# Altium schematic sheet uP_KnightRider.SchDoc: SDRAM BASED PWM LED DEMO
size A4; Engineer: SHOWELL; DocumentNumber: 1; Revision: 1.00; SheetNumber: 1; SheetTotal: 1
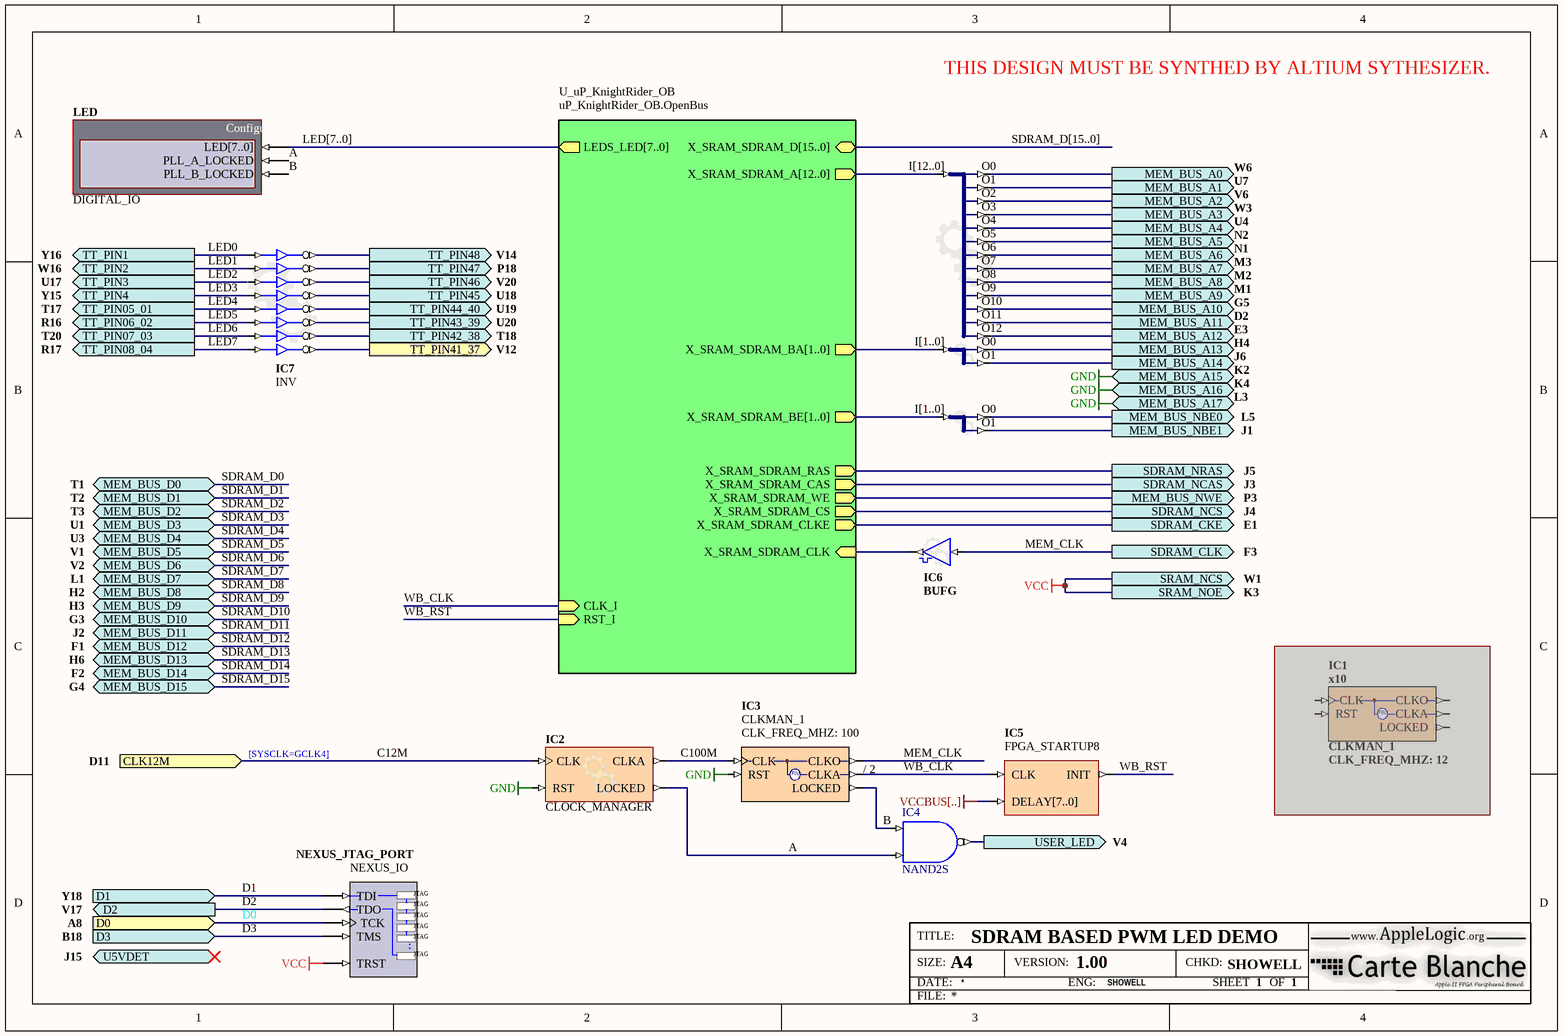
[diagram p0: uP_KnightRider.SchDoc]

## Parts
IC1  CLKMAN_1  CLK_FREQ_MHZ: 12  ClkA_Operation: x10  (masked out: inside a compile mask, not in the netlist)
IC2  CLOCK_MANAGER
IC3  CLKMAN_1  CLK_FREQ_MHZ: 100  ClkA_Operation: / 2
IC4  NAND2S
IC5  FPGA_STARTUP8
IC6  BUFG
IC7  INV
LED  DIGITAL_IO
NEXUS_JTAG_PORT  NEXUS_IO
U1011  BUS_JS  (value not drawn)
U1018  BUS_JS  (value not drawn)
U8011  BUS_JS  (value not drawn)

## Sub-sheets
U_uP_KnightRider_OB = uP_KnightRider_OB.OpenBus: LEDS_LED[7..0] (out), X_SRAM_SDRAM_D[15..0] (bidir), X_SRAM_SDRAM_A[12..0] (out), X_SRAM_SDRAM_BA[1..0] (out), X_SRAM_SDRAM_BE[1..0] (out), X_SRAM_SDRAM_RAS (out), X_SRAM_SDRAM_CAS (out), X_SRAM_SDRAM_WE (out), X_SRAM_SDRAM_CS (out), X_SRAM_SDRAM_CLKE (out), X_SRAM_SDRAM_CLK (in), RST_I (in), CLK_I (in)

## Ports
CLK12M (in, see D11), D0 (in, see A8), D1 (in, see Y18), D2 (out, see V17), D3 (in, see B18), MEM_BUS_A0 (out, see W6), MEM_BUS_A1 (out, see U7), MEM_BUS_A2 (out, see V6), MEM_BUS_A3 (out, see W3), MEM_BUS_A4 (out, see U4), MEM_BUS_A5 (out, see N2), MEM_BUS_A6 (out, see N1), MEM_BUS_A7 (out, see M3), MEM_BUS_A8 (out, see M2), MEM_BUS_A9 (out, see M1), MEM_BUS_A10 (out, see G5), MEM_BUS_A11 (out, see D2), MEM_BUS_A12 (out, see E3), MEM_BUS_A13 (out, see H4), MEM_BUS_A14 (out, see J6), MEM_BUS_A15 (out, see K2), MEM_BUS_A16 (out, see K4), MEM_BUS_A17 (out, see L3), MEM_BUS_D0 (bidir, see T1), MEM_BUS_D1 (bidir, see T2), MEM_BUS_D2 (bidir, see T3), MEM_BUS_D3 (bidir, see U1), MEM_BUS_D4 (bidir, see U3), MEM_BUS_D5 (bidir, see V1), MEM_BUS_D6 (bidir, see V2), MEM_BUS_D7 (bidir, see L1), MEM_BUS_D8 (bidir, see H2), MEM_BUS_D9 (bidir, see H3), MEM_BUS_D10 (bidir, see G3), MEM_BUS_D11 (bidir, see J2), MEM_BUS_D12 (bidir, see F1), MEM_BUS_D13 (bidir, see H6), MEM_BUS_D14 (bidir, see F2), MEM_BUS_D15 (bidir, see G4), MEM_BUS_NBE0 (out, see L5), MEM_BUS_NBE1 (out, see J1), MEM_BUS_NWE (out, see P3), SDRAM_CKE (out, see E1), SDRAM_CLK (out, see F3), SDRAM_NCAS (out, see J3), SDRAM_NCS (out, see J4), SDRAM_NRAS (out, see J5), SRAM_NCS (out, see W1), SRAM_NOE (out, see K3), TT_PIN1 (out, see Y16), TT_PIN2 (out, see W16), TT_PIN3 (out, see U17), TT_PIN4 (out, see Y15), TT_PIN05_01 (out, see T17), TT_PIN06_02 (out, see R16), TT_PIN07_03 (out, see T20), TT_PIN08_04 (out, see R17), TT_PIN41_37 (out, see V12), TT_PIN42_38 (out, see T18), TT_PIN43_39 (out, see U20), TT_PIN44_40 (out, see U19), TT_PIN45 (out, see U18), TT_PIN46 (out, see V20), TT_PIN47 (out, see P18), TT_PIN48 (out, see V14), U5VDET (in, see J15), USER_LED (out, see V4)

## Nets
GND: IC2.RST IC3.RST ; port MEM_BUS_A15, port MEM_BUS_A16, port MEM_BUS_A17
VCC: NEXUS_JTAG_PORT.TRST ; port SRAM_NOE, port SRAM_NCS
A: IC2.LOCKED IC4.I0 LED.PLL_A_LOCKED
B: IC3.LOCKED IC4.I1 LED.PLL_B_LOCKED
C12M: IC2.CLK ; port CLK12M
C100M: IC2.CLKA IC3.CLK
D0: NEXUS_JTAG_PORT.TCK ; port D0
D1: NEXUS_JTAG_PORT.TDI ; port D1
D2: NEXUS_JTAG_PORT.TDO ; port D2
D3: NEXUS_JTAG_PORT.TMS ; port D3
LED0: IC7.I0 ; port TT_PIN1
LED1: IC7.I1 ; port TT_PIN2
LED2: IC7.I2 ; port TT_PIN3
LED3: IC7.I3 ; port TT_PIN4
LED4: IC7.I4 ; port TT_PIN05_01
LED5: IC7.I5 ; port TT_PIN06_02
LED6: IC7.I6 ; port TT_PIN07_03
LED7: IC7.I7 ; port TT_PIN08_04
MEM_BUS_A0: U1018.O0 ; port MEM_BUS_A0
MEM_BUS_A1: U1018.O1 ; port MEM_BUS_A1
MEM_BUS_A2: U1018.O2 ; port MEM_BUS_A2
MEM_BUS_A3: U1018.O3 ; port MEM_BUS_A3
MEM_BUS_A4: U1018.O4 ; port MEM_BUS_A4
MEM_BUS_A5: U1018.O5 ; port MEM_BUS_A5
MEM_BUS_A6: U1018.O6 ; port MEM_BUS_A6
MEM_BUS_A7: U1018.O7 ; port MEM_BUS_A7
MEM_BUS_A8: U1018.O8 ; port MEM_BUS_A8
MEM_BUS_A9: U1018.O9 ; port MEM_BUS_A9
MEM_BUS_A10: U1018.O10 ; port MEM_BUS_A10
MEM_BUS_A11: U1018.O11 ; port MEM_BUS_A11
MEM_BUS_A12: U1018.O12 ; port MEM_BUS_A12
MEM_BUS_A13: U8011.O0 ; port MEM_BUS_A13
MEM_BUS_A14: U8011.O1 ; port MEM_BUS_A14
MEM_BUS_NBE0: U1011.O0 ; port MEM_BUS_NBE0
MEM_BUS_NBE1: U1011.O1 ; port MEM_BUS_NBE1
MEM_BUS_NWE: port MEM_BUS_NWE, sheet U_uP_KnightRider_OB/X_SRAM_SDRAM_WE
MEM_CLK: IC3.CLKO IC6.I ; port SDRAM_CLK
SDRAM_CKE: port SDRAM_CKE, sheet U_uP_KnightRider_OB/X_SRAM_SDRAM_CLKE
SDRAM_NCAS: port SDRAM_NCAS, sheet U_uP_KnightRider_OB/X_SRAM_SDRAM_CAS
SDRAM_NCS: port SDRAM_NCS, sheet U_uP_KnightRider_OB/X_SRAM_SDRAM_CS
SDRAM_NRAS: port SDRAM_NRAS, sheet U_uP_KnightRider_OB/X_SRAM_SDRAM_RAS
TT_PIN41_37: IC7.O7 ; port TT_PIN41_37
TT_PIN42_38: IC7.O6 ; port TT_PIN42_38
TT_PIN43_39: IC7.O5 ; port TT_PIN43_39
TT_PIN44_40: IC7.O4 ; port TT_PIN44_40
TT_PIN45: IC7.O3 ; port TT_PIN45
TT_PIN46: IC7.O2 ; port TT_PIN46
TT_PIN47: IC7.O1 ; port TT_PIN47
TT_PIN48: IC7.O0 ; port TT_PIN48
USER_LED: IC4.O ; port USER_LED
WB_CLK: IC3.CLKA IC5.CLK ; sheet U_uP_KnightRider_OB/CLK_I
WB_RST: IC5.INIT ; sheet U_uP_KnightRider_OB/RST_I
NetIC6_O: IC6.O ; sheet U_uP_KnightRider_OB/X_SRAM_SDRAM_CLK

Not connected (* = marked no-connect by the designer): IC5 DELAY[7..0]; LED LED[7..0]; U1011 I[1..0]; U1018 I[12..0]; U8011 I[1..0]

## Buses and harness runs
bus LED[7..0] = sheet U_uP_KnightRider_OB/LEDS_LED[7..0]
bus SDRAM_D[15..0] = sheet U_uP_KnightRider_OB/X_SRAM_SDRAM_D[15..0]

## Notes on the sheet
- THIS DESIGN MUST BE SYNTHED BY ALTIUM SYTHESIZER.
- [SYSCLK=GCLK4]
- Labels drawn without touching a wire or pin: VCCBUS[..]

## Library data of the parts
IC1 IC3 = CLKMAN_1: Single Operational Output Clock Manager; Clk_Count: 1
IC2 = CLOCKMANAGER: Configurable Clock Manager; ConfiguratorName: GENERIC_CLOCKMANAGER; ConfigurationParameters: {}Version[1.0]{}Option_Configuration[object _1: TClockManagerPersist / VersionMajor [ 0 / VersionMinor [ 0 / InputFreq [ 24.000000000000000000 / InputName [ 'CLK' / OutputTargets [ < / item / Name [ 'CLKA' / OutFreqMin [ 200.000000000000000000 / OutFreqMax [ 200.000000000000000000 / OutPostDivider [ 1.000000000000000000 / end> / OutputDevices [ < / item / Name [ 'Spartan3AN' / Valid [ True / OutputActuals [ < / item / Name [ 'CLK0' / Multipler [ 1.000000000000000000 / Divider [ 1.000000000000000000 / OutFreq [ 24.000000000000000000 / OutputMap [ 1 / end / item / Name [ 'CLK90' / Multipler [ 1.000000000000000000 / Divider [ 1.000000000000000000 / OutPhase [ 90.000000000000000000 / OutFreq [ 24.000000000000000000 / OutputMap [ 2 / end / item / Name [ 'CLK180' / Multipler [ 1.000000000000000000 / Divider [ 1.000000000000000000 / OutPhase [ 180.000000000000000000 / OutFreq [ 24.000000000000000000 / OutputMap [ 3 / end / item / Name [ 'CLK270' / Multipler [ 1.000000000000000000 / Divider [ 1.000000000000000000 / OutPhase [ 270.000000000000000000 / OutFreq [ 24.000000000000000000 / OutputMap [ 4 / end / item / Name [ 'CLK2X' / Multipler [ 2.000000000000000000 / Divider [ 1.000000000000000000 / OutFreq [ 48.000000000000000000 / OutputMap [ 5 / end / item / Name [ 'CLKDV' / Multipler [ 1.000000000000000000 / Divider [ 16.000000000000000000 / OutFreq [ 1.500000000000000000 / OutputMap [ 6 / end / item / Name [ 'CLK2X180' / Multipler [ 1.000000000000000000 / Divider [ 1.000000000000000000 / OutPhase [ 180.000000000000000000 / OutFreq [ 48.000000000000000000 / OutputMap [ 7 / end / item / Name [ 'CLKFX' / Multipler [ 25.000000000000000000 / Divider [ 3.000000000000000000 / OutFreq [ 200.000000000000000000 / OutputMap [ 0 / end / item / Name [ 'CLKFX180' / Multipler [ 1.000000000000000000 / Divider [ 1.000000000000000000 / OutPhase [ 180.000000000000000000 / OutFreq [ 200.000000000000000000 / OutputMap [ 8 / end> / InternalActuals [ <> / CustomVars [ <> / end> / MinInputFreq [ 1.000000000000000000 / MaxInputFreq [ 280.000000000000000000 / MinOutputFreq [ 18.000000000000000000 / MaxOutputFreq [ 210.000000000000000000 / MaxOutputCount [ 9 / end]{}
IC4 = NAND2: 2-Input NAND Gate, Single Pin Version; ArchiveName: GENERIC; XilinxEquivalent: NAND2; FunctionalClass: Logic Primitive; PortSize: 2; VHDLIB_SIM: GENERIC_LIB
IC5 = FPGA_STARTUP8: FPGA Startup With 8 Bit Delay
IC6 = BUFG: Configurable Global Clock Buffer; ConfiguratorName: GENERIC_BUFFER; ConfigurationParameters: {}Version[1.1]{}SignalCount[1]{}SignalWidth0[1]{}OutputOption0[Global Clock]{}EnableMode[None]{}ShowPinNames[False]{}
IC7 = INV: Configurable Inverter; ConfiguratorName: GENERIC_BUFFER; ConfigurationParameters: {}Version[1.1]{}SignalCount[8]{}SignalWidth0[1]{}OutputOption0[Inverted]{}SignalWidth1[1]{}OutputOption1[Inverted]{}SignalWidth2[1]{}OutputOption2[Inverted]{}SignalWidth3[1]{}OutputOption3[Inverted]{}SignalWidth4[1]{}OutputOption4[Inverted]{}SignalWidth5[1]{}OutputOption5[Inverted]{}SignalWidth6[1]{}OutputOption6[Inverted]{}SignalWidth7[1]{}OutputOption7[Inverted]{}EnableMode[None]{}ShowPinNames[False]{}
LED = DIGITAL_IO: Configurable Digital IO; NEXUS_CORE: Instrument; NEXUS_JTAG_DEVICE: True; NEXUS_JTAG_ORDER: 0; ConfigurationParameters: {}Version[2.0]{}StorageType[3]{}InterfaceType[Parallel]{}SchCompWidth[140]{}Input0Name[LED{1}7..0{2}]{}Input0Width[8]{}Input0InitValue[0]{}Input0Kind[LEDs]{}Input0LEDStyle[Green]{}Input1Name[PLL_A_LOCKED]{}Input1Width[1]{}Input1InitValue[0]{}Input1Kind[LEDs]{}Input1LEDStyle[Red]{}Input2Name[PLL_B_LOCKED]{}Input2Width[1]{}Input2InitValue[0]{}Input2Kind[LEDs]{}Input2LEDStyle[Red]{}NoOutputs[ ]{}Designator[LED]{}InternalID[0]{}
NEXUS_JTAG_PORT = NEXUS_JTAG_PORT: Soft Nexus-Chain Connector; NEXUS_JTAG_CONNECTOR: True
U1011 U8011 = BUS_JS: Configurable Bus Joiner/Splitter; ConfiguratorName: GENERIC_BUS_JS; ConfigurationParameters: {}Version[1.1]{}SplitterJoinerType[Splitter]{}SignalCount[2]{}SignalWidth0[1]{}GapBelow0[1000000]{}ConnectionType0[Pin]{}SignalWidth1[1]{}GapBelow1[1000000]{}ConnectionType1[Pin]{}ShowPinNames[True]{}
U1018 = BUS_JS: Configurable Bus Joiner/Splitter; ConfiguratorName: GENERIC_BUS_JS; ConfigurationParameters: {}Version[1.1]{}SplitterJoinerType[Splitter]{}SignalCount[13]{}SignalWidth0[1]{}GapBelow0[1000000]{}ConnectionType0[Pin]{}SignalWidth1[1]{}GapBelow1[1000000]{}ConnectionType1[Pin]{}SignalWidth2[1]{}GapBelow2[1000000]{}ConnectionType2[Pin]{}SignalWidth3[1]{}GapBelow3[1000000]{}ConnectionType3[Pin]{}SignalWidth4[1]{}GapBelow4[1000000]{}ConnectionType4[Pin]{}SignalWidth5[1]{}GapBelow5[1000000]{}ConnectionType5[Pin]{}SignalWidth6[1]{}GapBelow6[1000000]{}ConnectionType6[Pin]{}SignalWidth7[1]{}GapBelow7[1000000]{}ConnectionType7[Pin]{}SignalWidth8[1]{}GapBelow8[1000000]{}ConnectionType8[Pin]{}SignalWidth9[1]{}GapBelow9[1000000]{}ConnectionType9[Pin]{}SignalWidth10[1]{}GapBelow10[1000000]{}ConnectionType10[Pin]{}SignalWidth11[1]{}GapBelow11[1000000]{}ConnectionType11[Pin]{}SignalWidth12[1]{}GapBelow12[1000000]{}ConnectionType12[Pin]{}ShowPinNames[True]{}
